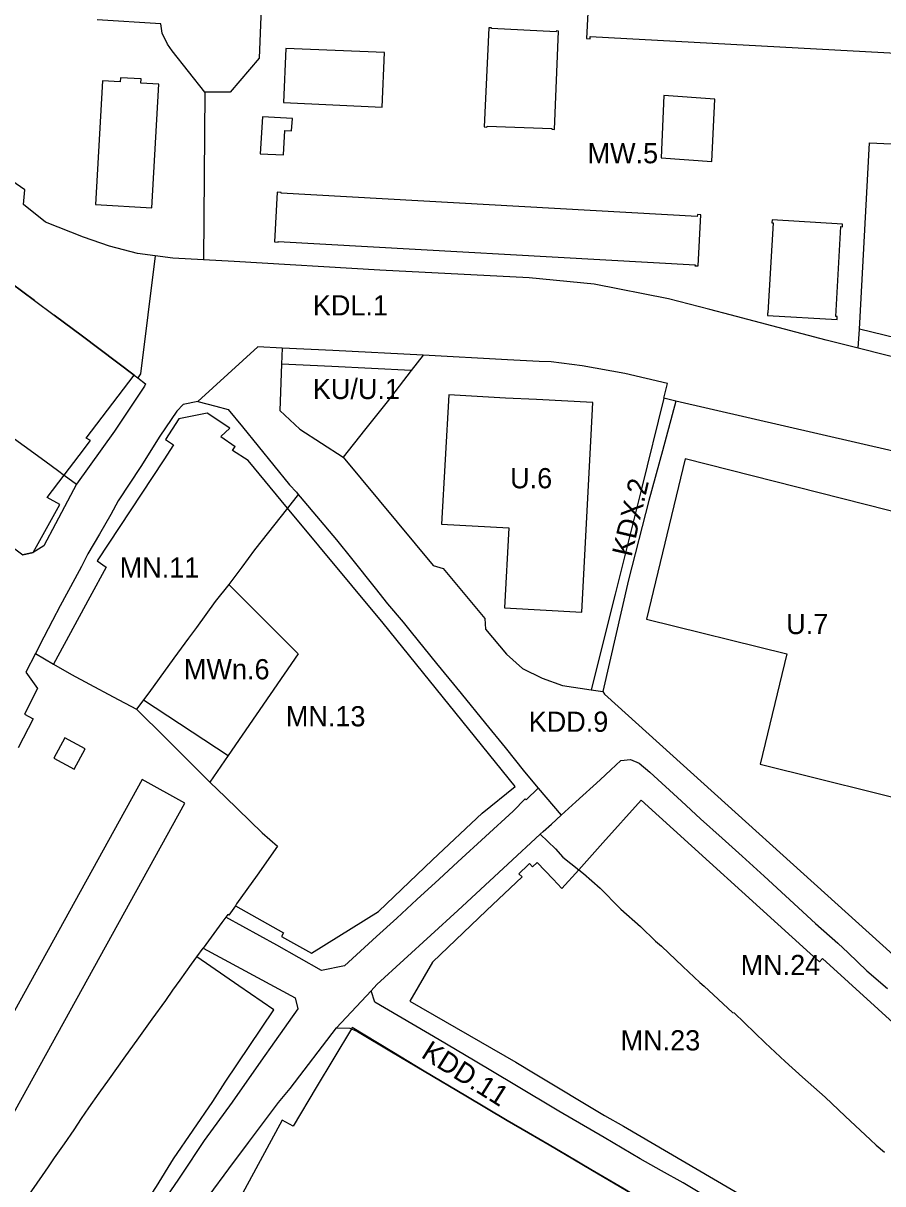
# Model space of a CAD drawing. Extents: x 7425067 to 7426806, y 5549054 to 5550619.
# Drawn here: x 7425798.3 to 7426010.9, y 5549976.3 to 5550263.3 of the extents above; entities that cross this region are included whole.
import ezdxf

# ---------------------------------------------------------------- set-up
doc = ezdxf.new("R2010")
doc.units = 0
for name, color, linetype in [('LIN_Linia Zabudowy Nieprzekraczalna', 7, 'Continuous'), ('LIN_linia zabudowy obowiązująca', 7, 'Continuous'), ('LIN_linie_rozgraniczajace', 7, 'Continuous'), ('TXT_Oznaczenia_przeznaczen', 7, 'Continuous')]:
    doc.layers.add(name, color=color, linetype=linetype)

msp = doc.modelspace()

# ---------------------------------------------------------------- linework, layer by layer
at = {"layer": 'LIN_Linia Zabudowy Nieprzekraczalna'}
for points in [[(7425801.06, 5550194.69), (7425789.46, 5550203.32)], [(7425801.06, 5550194.69), (7425805.9, 5550191.11)], [(7425812.93, 5550185.9), (7425805.9, 5550191.11)], [(7425825.7545, 5550176.2131), (7425812.93, 5550185.9)], [(7425862.1869, 5550178.9527), (7425861.75, 5550167.55), (7425866.68, 5550162.89), (7425877.38, 5550155.98)], [(7425894.2184, 5550177.366), (7425874.6332, 5550178.3548), (7425862.1869, 5550178.9527)], [(7425804.2366, 5550146.0168), (7425808.4189, 5550151.5429), (7425812.11, 5550156.42), (7425814.88, 5550160.08), (7425813.88, 5550160.69), (7425825.7545, 5550176.2131)], [(7425903.53, 5550171.36), (7425901.7445, 5550139.4109)], [(7425903.5798, 5550171.3571), (7425903.53, 5550171.36)], [(7425939.19, 5550169.46), (7425925.21, 5550170.21), (7425917.57, 5550170.55), (7425903.5798, 5550171.3571)], [(7425938.7622, 5550161.51), (7425939.19, 5550169.46)], [(7425847.19, 5550161.09), (7425849.38, 5550163.14), (7425843.77, 5550166.89), (7425836.79, 5550165.42), (7425833.48, 5550160.33), (7425835.43, 5550159)], [(7425847.19, 5550161.09), (7425850.73, 5550158.6)], [(7425936.4011, 5550117.6285), (7425938.7622, 5550161.51)], [(7425835.43, 5550159), (7425833.07, 5550155.35), (7425816.55, 5550130.38)], [(7425853.9, 5550155.13), (7425850.04, 5550157.59), (7425850.73, 5550158.6)], [(7425919.93, 5550074.58), (7425887.27, 5550114.89), (7425863.64, 5550143.3848), (7425853.9, 5550155.13)], [(7425961.9593, 5550155.5419), (7425952.4016, 5550115.8997)], [(7426039.6759, 5550135.8352), (7425961.9593, 5550155.5419)], [(7425807.33, 5550144.23), (7425804.2366, 5550146.0168)], [(7425788.73, 5550138.84), (7425798.17, 5550131.83), (7425800.74, 5550132.42), (7425807.33, 5550144.23)], [(7425901.7445, 5550139.4109), (7425918.4237, 5550138.476)], [(7425918.4237, 5550138.476), (7425917.2875, 5550118.6998)], [(7425818.7603, 5550128.736), (7425814.73, 5550121.33), (7425805.7382, 5550104.8069)], [(7425816.55, 5550130.38), (7425818.7603, 5550128.736)], [(7425917.2875, 5550118.6998), (7425936.4011, 5550117.6285)], [(7425952.4016, 5550115.8997), (7425987.1112, 5550107.3078)], [(7425987.1112, 5550107.3078), (7425980.542, 5550080.0607)], [(7425828.0428, 5550095.996), (7425848.9976, 5550082.196)], [(7425980.542, 5550080.0607), (7426023.0148, 5550069.5471)], [(7425886.14, 5550043.62), (7425899.5, 5550056.43), (7425911.77, 5550067.96), (7425919.93, 5550074.58)], [(7425850.7403, 5550045.0381), (7425862.66, 5550038.39), (7425862.14, 5550037.46), (7425869.58, 5550033.3), (7425886.14, 5550043.62)], [(7425860.25, 5550019.29), (7425851.58, 5550025.27), (7425841.2304, 5550032.4085)], [(7425742.7389, 5549884.8292), (7425754.78, 5549877.53), (7425763.82, 5549872.05), (7425777.59, 5549894.86), (7425782.97, 5549902.92), (7425793.7, 5549919.37), (7425798.37, 5549926.6), (7425805.55, 5549937.49), (7425810.05, 5549943.84), (7425813.5, 5549948.98), (7425818.04, 5549956.33), (7425822.22, 5549961.9), (7425831.24, 5549975.65), (7425835.44, 5549982.46), (7425845.17, 5549996.67), (7425848.22, 5550001.39), (7425860.25, 5550019.29)], [(7425879.6191, 5550014.9366), (7425879.4377, 5550014.6334), (7425870.75, 5550000.11), (7425865.0095, 5549990.5135)], [(7425862.3081, 5549992.0502), (7425852.01, 5549973.01), (7425887.6133, 5549953.5801), (7425989.492, 5549897.9817)], [(7425865.0095, 5549990.5135), (7425862.3081, 5549992.0502)]]:
    msp.add_lwpolyline(points, dxfattribs=at)
at = {"layer": 'LIN_linia zabudowy obowiązująca'}
for points in [[(7425938.98, 5550271.63), (7425939.01, 5550272.24), (7425938.25, 5550272.28), (7425937.56, 5550259.5), (7425938.5, 5550259.45), (7425938.53, 5550259.97), (7426041.36, 5550254.4), (7426041.33, 5550253.87), (7426042.05, 5550253.83), (7426042.74, 5550266.45), (7426042.01, 5550266.48), (7426041.99, 5550266.06), (7425938.98, 5550271.63)], [(7425912.25, 5550237.64), (7425912.92, 5550237.6), (7425913.02, 5550237.81), (7425929.06, 5550237.24), (7425929.03, 5550237.05), (7425929.67, 5550237.02), (7425930.71, 5550261.27), (7425930.19, 5550261.35), (7425930.13, 5550261.13), (7425914.09, 5550261.95), (7425914.09, 5550262.12), (7425913.45, 5550262.12), (7425912.25, 5550237.64)], [(7425863.2541, 5550257.0538), (7425862.69, 5550243.64)], [(7425887.6731, 5550256.0034), (7425863.2541, 5550257.0538)], [(7425887.09, 5550242.55), (7425887.6731, 5550256.0034)], [(7425830.11, 5550217.66), (7425831.85, 5550248.21), (7425827.38, 5550248.47), (7425827.43, 5550249.51), (7425822.34, 5550249.8), (7425822.28, 5550248.74), (7425817.89, 5550248.99), (7425816.16, 5550218.45), (7425830.11, 5550217.66)], [(7425862.69, 5550243.64), (7425887.09, 5550242.55)], [(7425956.72, 5550245.44), (7425956.05, 5550229.97), (7425968.57, 5550229.11), (7425969.32, 5550244.5), (7425956.72, 5550245.44)], [(7425857.42, 5550240.15), (7425856.91, 5550231.01), (7425862.68, 5550230.69), (7425863.02, 5550236.78), (7425864.66, 5550236.68), (7425864.85, 5550239.71), (7425857.42, 5550240.15)], [(7425964.98, 5550215.51), (7425862.08, 5550221.25), (7425862.06, 5550221.43), (7425861.1, 5550221.53), (7425860.46, 5550209.22), (7425861.33, 5550209.15), (7425861.37, 5550209.31), (7425964.46, 5550203.55), (7425964.4, 5550203.28), (7425965.25, 5550203.26), (7425965.9, 5550215.89), (7425965.08, 5550215.98), (7425964.98, 5550215.51)], [(7426000.52, 5550212.98), (7426000.91, 5550212.96), (7426000.94, 5550213.61), (7425983.5, 5550214.62), (7425983.46, 5550213.95), (7425983.77, 5550213.93), (7425982.48, 5550191.68), (7425982.37, 5550191.69), (7425982.33, 5550191.01), (7425999.58, 5550190), (7425999.62, 5550190.73), (7425999.23, 5550190.75), (7426000.52, 5550212.98)], [(7425808.55, 5550086.55), (7425805.84, 5550081.53), (7425810.87, 5550078.82), (7425813.57, 5550083.83), (7425808.55, 5550086.55)], [(7425827.66, 5550076.24), (7425771.07, 5549973.79)], [(7425771.07, 5549973.79), (7425781.44, 5549967.75), (7425838.25, 5550070.38), (7425827.66, 5550076.24)], [(7425951.14, 5550071.13), (7425941.66, 5550060.59), (7425935.6649, 5550053.9246), (7425931.502, 5550049.2962)], [(7426037.21, 5549992.85), (7426035.62, 5549994.38), (7426036.39, 5549995.22), (7425995.96, 5550031.98), (7425995.21, 5550031.16), (7425992.89, 5550033.28), (7425951.14, 5550071.13)], [(7425924.2354, 5550054.671), (7425923.48, 5550055.47), (7425923.19, 5550055.2), (7425920.88, 5550052.97), (7425921.68, 5550052.2), (7425912.86, 5550043.85)], [(7425924.2354, 5550054.671), (7425925.3793, 5550055.7591)], [(7425931.502, 5550049.2962), (7425929.31, 5550051.61), (7425925.3793, 5550055.7591)], [(7425912.86, 5550043.85), (7425899.49, 5550031.08), (7425893.9, 5550021.45)], [(7425893.9, 5550021.45), (7425920.1, 5550006.36), (7425924.87, 5550003.45), (7425942.08, 5549993.19), (7425946.76, 5549990.58), (7425980.13, 5549971.02), (7425987.76, 5549966.48), (7425995.01, 5549962.2), (7426000.79, 5549958.61), (7426013.79, 5549950.82), (7426019.11, 5549959.62), (7426025.8248, 5549970.7272), (7426030.7315, 5549978.8436)], [(7426010.59, 5549937.36), (7426000.75, 5549943.29), (7425993.84, 5549947.42), (7425990.41, 5549949.38), (7425987.07, 5549951.43), (7425980.16, 5549955.59), (7425969.84, 5549961.68), (7425959.38, 5549967.72), (7425952.35, 5549971.75), (7425948.86, 5549973.84), (7425946.62, 5549975.18), (7425938.68, 5549979.84), (7425932.98, 5549983.21), (7425928.33, 5549985.92), (7425923.28, 5549988.93), (7425917.99, 5549991.99), (7425907.79, 5549998.04), (7425897.42, 5550004.16), (7425889.48, 5550009.02), (7425879.6191, 5550014.9366)]]:
    msp.add_lwpolyline(points, dxfattribs=at)
at = {"layer": 'LIN_linie_rozgraniczajace'}
for points in [[(7425857.1227, 5550267.0118), (7425856.64, 5550254.66)], [(7425832.32, 5550263.1), (7425816.57, 5550264.13)], [(7425832.61, 5550260.81), (7425832.32, 5550263.1)], [(7425833.93, 5550258.1), (7425832.61, 5550260.81)], [(7425835.155, 5550256.46), (7425833.93, 5550258.1)], [(7425843.17, 5550246.24), (7425835.155, 5550256.46)], [(7425856.64, 5550254.66), (7425849.48, 5550246.23)], [(7425843.17, 5550246.24), (7425842.85, 5550204.765)], [(7425849.48, 5550246.23), (7425843.17, 5550246.24)], [(7425798.69, 5550222.07), (7425782.29, 5550233.35)], [(7426005.08, 5550187.64), (7426007.59, 5550233.71)], [(7426007.59, 5550233.71), (7426012.9642, 5550233.4679), (7426019.06, 5550233.19)], [(7425798.37, 5550218.47), (7425798.69, 5550222.07)], [(7425803.78, 5550214.06), (7425798.37, 5550218.47)], [(7425813.18, 5550210.37), (7425803.78, 5550214.06)], [(7425819.65, 5550208.15), (7425813.18, 5550210.37)], [(7425826.55, 5550206.32), (7425819.65, 5550208.15)], [(7425830.92, 5550205.755), (7425826.55, 5550206.32)], [(7425830.92, 5550205.755), (7425827.3, 5550176.55)], [(7425835.29, 5550205.19), (7425830.92, 5550205.755)], [(7425789.46, 5550203.32), (7425801.06, 5550194.69)], [(7425850.41, 5550204.34), (7425842.85, 5550204.765), (7425835.29, 5550205.19)], [(7425886.45, 5550202.22), (7425850.41, 5550204.34)], [(7425923.43, 5550200.28), (7425886.45, 5550202.22)], [(7425939.47, 5550198.73), (7425923.43, 5550200.28)], [(7425957.87, 5550195.11), (7425939.47, 5550198.73)], [(7425801.06, 5550194.69), (7425805.9, 5550191.11)], [(7425968.07, 5550192.5), (7425957.87, 5550195.11)], [(7425973.09, 5550191.16), (7425968.07, 5550192.5)], [(7425805.9, 5550191.11), (7425812.93, 5550185.9)], [(7425996.91, 5550184.93), (7425973.09, 5550191.16)], [(7425812.93, 5550185.9), (7425825.7545, 5550176.2131), (7425826.6198, 5550175.5595)], [(7426004.8269, 5550182.9338), (7426005.08, 5550187.64)], [(7426069.19, 5550172.05), (7426005.08, 5550187.64)], [(7425856.3176, 5550183.2663), (7425841.44, 5550169.75)], [(7425862.34, 5550182.95), (7425856.3176, 5550183.2663)], [(7425862.34, 5550182.95), (7425862.1869, 5550178.9527), (7425861.75, 5550167.55)], [(7425874.83, 5550182.35), (7425862.34, 5550182.95)], [(7426004.8269, 5550182.9338), (7425996.91, 5550184.93)], [(7426038.38, 5550174.46), (7426004.8269, 5550182.9338)], [(7425897.21, 5550181.22), (7425874.83, 5550182.35)], [(7425897.21, 5550181.22), (7425894.2184, 5550177.366), (7425888.26, 5550169.69)], [(7425918.08, 5550180.07), (7425897.21, 5550181.22)], [(7425925.88, 5550179.61), (7425918.08, 5550180.07)], [(7425928.88, 5550179.51), (7425925.88, 5550179.61)], [(7425936.53, 5550178.55), (7425928.88, 5550179.51)], [(7425947.09, 5550176.66), (7425936.53, 5550178.55)], [(7425827.3, 5550176.55), (7425826.6198, 5550175.5595)], [(7425826.6198, 5550175.5595), (7425828.5173, 5550174.1262)], [(7425957.66, 5550174.21), (7425947.09, 5550176.66)], [(7425956.7483, 5550170.5534), (7425957.66, 5550174.21)], [(7425828.09, 5550173.29), (7425820.81, 5550162.41)], [(7425828.25, 5550173.55), (7425828.09, 5550173.29)], [(7425828.5173, 5550174.1262), (7425828.25, 5550173.55)], [(7425837.82, 5550168.99), (7425836.27, 5550167.35)], [(7425841.44, 5550169.75), (7425837.82, 5550168.99)], [(7425841.44, 5550169.75), (7425845.8894, 5550168.5678)], [(7425845.8894, 5550168.5678), (7425848.93, 5550167.76)], [(7425888.26, 5550169.69), (7425882.66, 5550162.64)], [(7425956.7483, 5550170.5534), (7425951.165, 5550148.16)], [(7425959.73, 5550169.81), (7425956.385, 5550157.53)], [(7425959.73, 5550169.81), (7425956.7483, 5550170.5534)], [(7425986.58, 5550163.62), (7425959.73, 5550169.81)], [(7425836.27, 5550167.35), (7425832.095, 5550161.175)], [(7425848.93, 5550167.76), (7425852.5, 5550163.5)], [(7425861.75, 5550167.55), (7425866.68, 5550162.89)], [(7425852.5, 5550163.5), (7425864.1, 5550149.13)], [(7425866.68, 5550162.89), (7425877.38, 5550155.98)], [(7426013.43, 5550157.43), (7425986.58, 5550163.62)], [(7425796.12, 5550160.52), (7425798.48, 5550158.74)], [(7425820.81, 5550162.41), (7425811.43, 5550149.31)], [(7425832.095, 5550161.175), (7425827.37, 5550153.7)], [(7425882.66, 5550162.64), (7425877.38, 5550155.98)], [(7425798.48, 5550158.74), (7425803.61, 5550155.06)], [(7425956.385, 5550157.53), (7425953.04, 5550145.25)], [(7425803.61, 5550155.06), (7425807.09, 5550152.53)], [(7425877.38, 5550155.98), (7425899.66, 5550129.2)], [(7425807.09, 5550152.53), (7425808.18, 5550151.72)], [(7425808.18, 5550151.72), (7425808.4189, 5550151.5429), (7425811.43, 5550149.31)], [(7425827.37, 5550153.7), (7425821.77, 5550145.16)], [(7425811.43, 5550149.31), (7425806.24, 5550139.5)], [(7425864.1, 5550149.13), (7425865.84, 5550147.35)], [(7425866.31, 5550146.75), (7425863.64, 5550143.3848), (7425855.48, 5550133.1)], [(7425865.84, 5550147.35), (7425866.31, 5550146.75)], [(7425866.31, 5550146.75), (7425866.78, 5550146.15)], [(7425866.78, 5550146.15), (7425875.73, 5550135.5)], [(7425951.165, 5550148.16), (7425944.67, 5550122.11)], [(7425821.77, 5550145.16), (7425819.98, 5550141.78)], [(7425953.04, 5550145.25), (7425947.95, 5550125.62)], [(7425819.98, 5550141.78), (7425817.13, 5550136.945)], [(7425806.24, 5550139.5), (7425803.357, 5550134.0506)], [(7425817.13, 5550136.945), (7425814.28, 5550132.11)], [(7425803.357, 5550134.0506), (7425800.74, 5550132.42)], [(7425875.73, 5550135.5), (7425879.48, 5550130.89)], [(7425800.74, 5550132.42), (7425798.17, 5550131.83)], [(7425814.28, 5550132.11), (7425812.66, 5550128.94)], [(7425855.48, 5550133.1), (7425852.315, 5550128.805)], [(7425812.66, 5550128.94), (7425811.01, 5550125.855)], [(7425852.315, 5550128.805), (7425849.15, 5550124.51)], [(7425879.48, 5550130.89), (7425885.36, 5550123.56)], [(7425899.66, 5550129.2), (7425902.15, 5550128.47)], [(7425902.15, 5550128.47), (7425912.46, 5550116.09)], [(7425811.01, 5550125.855), (7425807.435, 5550119.175)], [(7425947.95, 5550125.62), (7425941.66, 5550098.04)], [(7425849.15, 5550124.51), (7425852.2066, 5550121.4336), (7425855.43, 5550118.21), (7425859.62, 5550114), (7425866.25, 5550107.33), (7425848.9976, 5550082.196), (7425844.47, 5550075.6)], [(7425849.15, 5550124.51), (7425845.71, 5550120.26)], [(7425885.36, 5550123.56), (7425888.39, 5550119.69)], [(7425845.71, 5550120.26), (7425841.13, 5550113.835)], [(7425888.39, 5550119.69), (7425892.27, 5550115.14)], [(7425944.67, 5550122.11), (7425938.76, 5550098.43)], [(7425807.435, 5550119.175), (7425805.51, 5550115.58)], [(7425805.51, 5550115.58), (7425803.41, 5550111.49)], [(7425892.27, 5550115.14), (7425894.2, 5550112.69)], [(7425912.46, 5550116.09), (7425912.61, 5550113.47)], [(7425803.41, 5550111.49), (7425801.31, 5550107.4)], [(7425839.18, 5550111.23), (7425835.555, 5550106.25)], [(7425841.13, 5550113.835), (7425839.18, 5550111.23)], [(7425894.2, 5550112.69), (7425897.35, 5550108.83)], [(7425912.61, 5550113.47), (7425917.83, 5550107.28)], [(7425897.35, 5550108.83), (7425900.5, 5550104.97)], [(7425801.31, 5550107.4), (7425798.94, 5550102.85)], [(7425801.31, 5550107.4), (7425805.7382, 5550104.8069), (7425810.19, 5550102.2)], [(7425835.555, 5550106.25), (7425831.93, 5550101.27)], [(7425917.83, 5550107.28), (7425921.79, 5550103.68)], [(7425798.94, 5550102.85), (7425801.84, 5550098.8)], [(7425900.5, 5550104.97), (7425906.565, 5550097.555)], [(7425921.79, 5550103.68), (7425926.6, 5550101.3)], [(7425810.19, 5550102.2), (7425814.69, 5550099.81)], [(7425814.69, 5550099.81), (7425820.48, 5550096.745)], [(7425831.93, 5550101.27), (7425829.37, 5550097.73)], [(7425926.6, 5550101.3), (7425931.69, 5550099.5)], [(7425801.84, 5550098.8), (7425798.5779, 5550092.3867)], [(7425820.48, 5550096.745), (7425826.27, 5550093.68)], [(7425829.37, 5550097.73), (7425828.0428, 5550095.996), (7425827.82, 5550095.705)], [(7425906.565, 5550097.555), (7425912.63, 5550090.14)], [(7425931.69, 5550099.5), (7425938.76, 5550098.43)], [(7425938.76, 5550098.43), (7425941.66, 5550098.04)], [(7425941.66, 5550098.04), (7425942.03, 5550097.4)], [(7425942.03, 5550097.4), (7426021.15, 5550025.96)], [(7425827.82, 5550095.705), (7425826.27, 5550093.68)], [(7425800.705, 5550091.3047), (7425797.03, 5550084.0798)], [(7425798.5779, 5550092.3867), (7425800.705, 5550091.3047)], [(7425826.27, 5550093.68), (7425833.54, 5550086.46)], [(7425912.63, 5550090.14), (7425917.45, 5550084.155)], [(7425833.54, 5550086.46), (7425840.81, 5550079.24)], [(7425917.45, 5550084.155), (7425922.27, 5550078.17)], [(7425943.62, 5550078.7), (7425946.09, 5550081)], [(7425946.09, 5550081), (7425948.44, 5550081.18)], [(7425948.44, 5550081.18), (7425950.61, 5550080.34)], [(7425950.61, 5550080.34), (7425953.23, 5550078.08)], [(7425840.81, 5550079.24), (7425844.47, 5550075.6)], [(7425922.27, 5550078.17), (7425925.68, 5550074.13)], [(7425940.97, 5550076.21), (7425942.295, 5550077.455)], [(7425942.295, 5550077.455), (7425943.62, 5550078.7)], [(7425953.23, 5550078.08), (7425961.12, 5550070.94)], [(7425844.47, 5550075.6), (7425848.3, 5550071.88)], [(7425925.68, 5550074.13), (7425922.7, 5550071.21)], [(7425925.68, 5550074.13), (7425931.3279, 5550067.4386)], [(7425934.935, 5550070.72), (7425940.97, 5550076.21)], [(7425848.3, 5550071.88), (7425857.34, 5550063.11)], [(7425922.42, 5550071.49), (7425919.48, 5550068.47)], [(7425922.7, 5550071.21), (7425922.42, 5550071.49)], [(7425961.12, 5550070.94), (7425965.81, 5550066.53)], [(7425919.48, 5550068.47), (7425905.76, 5550055.88)], [(7425926.16, 5550062.74), (7425926.9, 5550063.41), (7425928.9, 5550065.23), (7425931.3279, 5550067.4386), (7425934.935, 5550070.72)], [(7425965.81, 5550066.53), (7425971.13, 5550061.79)], [(7425857.34, 5550063.11), (7425861.15, 5550059.75)], [(7425918.15, 5550055.31), (7425926.16, 5550062.74)], [(7425926.16, 5550062.74), (7425929.89, 5550059.13), (7425931.71, 5550057.07)], [(7425861.15, 5550059.75), (7425856.105, 5550052.62)], [(7425971.13, 5550061.79), (7425976.08, 5550057.3)], [(7425931.71, 5550057.07), (7425935.6649, 5550053.9246), (7425936.84, 5550052.99)], [(7425976.08, 5550057.3), (7425981.51, 5550052.34)], [(7425905.76, 5550055.88), (7425901.115, 5550051.605)], [(7425905.81, 5550043.87), (7425918.15, 5550055.31)], [(7425856.105, 5550052.62), (7425851.06, 5550045.49)], [(7425901.115, 5550051.605), (7425895.67, 5550046.6)], [(7425936.84, 5550052.99), (7425940.96, 5550049.39), (7425941.2, 5550049.15)], [(7425981.51, 5550052.34), (7425986.84, 5550047.48)], [(7425941.2, 5550049.15), (7425945.63, 5550044.7), (7425946.12, 5550044.18)], [(7425851.06, 5550045.49), (7425850.7403, 5550045.0381), (7425849.12, 5550042.75)], [(7425895.67, 5550046.6), (7425890.645, 5550042.005)], [(7425986.84, 5550047.48), (7425994.26, 5550040.67)], [(7425848.4, 5550042.24), (7425847.39, 5550040.87)], [(7425848.86, 5550042.89), (7425848.4, 5550042.24)], [(7425860.98, 5550035.34), (7425848.4, 5550042.24)], [(7425849.12, 5550042.75), (7425848.86, 5550042.89)], [(7425885.7, 5550025.59), (7425905.81, 5550043.87)], [(7425946.12, 5550044.18), (7425950.96, 5550039.9)], [(7425847.39, 5550040.87), (7425842.77, 5550034.54)], [(7425890.645, 5550042.005), (7425885.62, 5550037.41)], [(7425950.96, 5550039.9), (7425954.63, 5550036.3)], [(7425994.26, 5550040.67), (7425999.72, 5550035.81)], [(7425885.62, 5550037.41), (7425877.74, 5550030.18)], [(7425839.935, 5550030.615), (7425841.2304, 5550032.4085), (7425842.77, 5550034.54)], [(7425842.77, 5550034.54), (7425865.53, 5550022.26)], [(7425872.09, 5550029.03), (7425860.98, 5550035.34)], [(7425954.63, 5550036.3), (7425956.11, 5550035.06)], [(7425956.11, 5550035.06), (7425961.43, 5550030.02)], [(7425999.72, 5550035.81), (7426002.34, 5550033.42)], [(7426002.34, 5550033.42), (7426006.97, 5550029)], [(7425837.1, 5550026.69), (7425839.935, 5550030.615)], [(7425877.74, 5550030.18), (7425872.09, 5550029.03)], [(7425961.43, 5550030.02), (7425965.61, 5550026.08)], [(7426006.97, 5550029), (7426012.02, 5550024.58)], [(7425835.31, 5550024.17), (7425837.1, 5550026.69)], [(7425884.33, 5550023.98), (7425885.7, 5550025.59)], [(7425965.61, 5550026.08), (7425966.66, 5550025.17)], [(7425966.66, 5550025.17), (7425973.68, 5550018.62), (7425974.11, 5550018.55)], [(7425833.52, 5550021.65), (7425835.31, 5550024.17)], [(7425865.53, 5550022.26), (7425866.16, 5550019.55)], [(7425875.79, 5550014.85), (7425884.33, 5550023.98)], [(7425885.23, 5550021.24), (7425884.33, 5550023.98)], [(7425830.18, 5550017.015), (7425833.52, 5550021.65)], [(7425866.16, 5550019.55), (7425860.46, 5550011.44)], [(7425901.13, 5550011.87), (7425885.23, 5550021.24)], [(7425826.84, 5550012.38), (7425830.18, 5550017.015)], [(7425974.11, 5550018.55), (7425981.8, 5550011.15)], [(7425864.32, 5549999.89), (7425875.79, 5550014.85)], [(7425875.79, 5550014.85), (7425879.08, 5550014.8)], [(7425879.08, 5550014.8), (7425879.4377, 5550014.6334), (7425880.97, 5550013.92)], [(7425880.97, 5550013.92), (7425889.36, 5550008.92)], [(7425823.22, 5550007.335), (7425826.84, 5550012.38)], [(7425860.46, 5550011.44), (7425857.07, 5550006.64)], [(7425909.63, 5550006.88), (7425901.13, 5550011.87)], [(7425981.8, 5550011.15), (7425986.72, 5550006.58)], [(7425889.36, 5550008.92), (7425897.42, 5550004.16)], [(7425819.6, 5550002.29), (7425823.22, 5550007.335)], [(7425857.07, 5550006.64), (7425849.93, 5549996.5)], [(7425919.9, 5550000.78), (7425909.63, 5550006.88)], [(7425986.72, 5550006.58), (7425991.03, 5550002.69)], [(7425817.07, 5549998.685), (7425819.6, 5550002.29)], [(7425897.42, 5550004.16), (7425907.79, 5549998.04)], [(7425991.03, 5550002.69), (7425996.59, 5549997.69)], [(7425861.38, 5549996.39), (7425864.32, 5549999.89)], [(7425930.76, 5549994.28), (7425919.9, 5550000.78)], [(7425814.54, 5549995.08), (7425817.07, 5549998.685)], [(7425849.93, 5549996.5), (7425843.07, 5549986.98)], [(7425853.96, 5549986.52), (7425861.38, 5549996.39)], [(7425907.79, 5549998.04), (7425917.99, 5549991.99)], [(7425996.59, 5549997.69), (7426001.58, 5549993.04)], [(7425812.71, 5549992.47), (7425814.54, 5549995.08)], [(7425941.94, 5549987.71), (7425930.76, 5549994.28)], [(7425810.87, 5549989.65), (7425812.71, 5549992.47)], [(7425917.99, 5549991.99), (7425923.28, 5549988.93)], [(7426001.58, 5549993.04), (7426007.87, 5549987.16)], [(7425808.445, 5549986.17), (7425810.87, 5549989.65)], [(7425923.28, 5549988.93), (7425928.33, 5549985.92)], [(7425950.89, 5549982.48), (7425941.94, 5549987.71)], [(7425806.02, 5549982.69), (7425808.445, 5549986.17)], [(7425843.07, 5549986.98), (7425837.35, 5549978.44)], [(7425849.1, 5549979.97), (7425853.96, 5549986.52)], [(7425928.33, 5549985.92), (7425938.68, 5549979.84)], [(7426007.87, 5549987.16), (7426009.24, 5549985.88)], [(7426009.24, 5549985.88), (7426011.31, 5549984.11)], [(7425804.52, 5549980.525), (7425806.02, 5549982.69)], [(7425956.18, 5549979.515), (7425950.89, 5549982.48)], [(7425803.02, 5549978.36), (7425804.52, 5549980.525)], [(7425844.24, 5549973.42), (7425849.1, 5549979.97)], [(7425938.68, 5549979.84), (7425948.86, 5549973.84)], [(7425961.47, 5549976.55), (7425956.18, 5549979.515)], [(7425799.07, 5549972.68), (7425801.69, 5549976.45)], [(7425801.69, 5549976.45), (7425803.02, 5549978.36)], [(7425836.48, 5549977.19), (7425829.63, 5549967.12)], [(7425837.35, 5549978.44), (7425836.48, 5549977.19)], [(7425971.8, 5549970.34), (7425961.47, 5549976.55)]]:
    msp.add_lwpolyline(points, dxfattribs=at)
at = {"layer": 'TXT_Oznaczenia_przeznaczen'}
msp.add_line((7425992.22, 5550214.115), (7425992.22, 5550214.115), dxfattribs=at)

# ---------------------------------------------------------------- texts
for s, p in [('MW.5', (7425937.8505, 5550228.6424)), ('KDL.1', (7425869.9122, 5550191.0194)), ('KU/U.1', (7425869.9122, 5550170.3366)), ('U.6', (7425918.6949, 5550148.274)), ('MN.11', (7425822.1294, 5550126.1813)), ('U.7', (7425986.994, 5550112.2217)), ('MWn.6', (7425838.0216, 5550101.0381)), ('MN.13', (7425863.2297, 5550089.4098)), ('KDD.9', (7425923.3, 5550088.0597)), ('MN.24', (7425975.7138, 5550027.8978)), ('MN.23', (7425946.0295, 5550009.2767))]:
    msp.add_text(s, height=5, dxfattribs=at).set_placement(p)
for s, rotation, p in [('KDX.2', 76.990883, (7425948.718, 5550131.1453)), ('KDD.11', 327.697699, (7425896.4312, 5550007.7289))]:
    msp.add_text(s, height=5, rotation=rotation, dxfattribs=at).set_placement(p)

doc.saveas('drawing.dxf')
